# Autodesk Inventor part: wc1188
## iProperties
Shininess: 64.0
Length Units: 11272
Angle Units: 11279
Time Units: 11290
Mass Units: 11286
Length Display Precision: 3
Angle Display Precision: 2
Compacted: True
Part Number: wc1188
Document SubType Name: Modeling
Created: 2004-08
Designer: John Blackburn
Manufacturer: Standard
Standards Organization: Custom
Material: Stainless Steel, Austenitic
Density: 0.0
Volumn: 0.0
Area: 0.0
PropertySet Name: Model Information
Control State: 0
Master: False
Checked Out: False
Author: John Blackburn
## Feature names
1. Base1
